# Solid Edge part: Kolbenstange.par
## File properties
Username: bmolnar
Dokumentum tartalom típus: 0
Author: bmolnar
Last saved by: bmolnar
Revision: 82
Sűrűség: 0,000 kg/m^3
Pontosság: 0,990
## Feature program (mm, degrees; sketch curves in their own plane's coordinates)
base feature "unnamed BaseFeature 1"
sketch for "unnamed Protrusion 1" plane through (42.5, 0, 0) normal (1, 0, 0) x-axis (0, 0, -1)
  circle centre (0, 0) radius 31.5
extrude "unnamed Protrusion 1" add finite 17.85 along +normal
sketch for "Kihúzás_2" #1 plane through (42.5, 0, 0) normal (1, 0, 0) x-axis (0, 0, -1)
  circle centre (0, 0) radius 8
sketch for "Kihúzás_2" #2 plane through (42.5, 0, 0) normal (1, 0, 0) x-axis (0, 0, -1)
  circle centre (0, 0) radius 31.5
extrude "Kihúzás_2" add finite 11 along -normal
sketch for "Furat_1" plane through (-17, 0, 0.0012) normal (-1, 0, 0) x-axis (0, 0, 1)
  hole centre (-0.0012, 0) bore radius 3.3235
hole "Furat_1" nominal diameter 8 finite  VBottomAngle = 118 deg; ThreadDepth = 14 mm
chamfer "Letörés_1" setback 0.7  SetBackValue2 = 45 deg
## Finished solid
Body 1: solid body, 16 faces, 22 edges, 8 vertices.
  Faces by surface: plane 8, cylinder 5, cone 2, torus 1
  Edges by curve: circle 12, line 6, curve on surface 2, ellipse 2
Bounding box of the edges (mm; curved faces can reach further): 80.350 x 63.000 x 63.000, from (-20, -31.5, -31.5) to (60.35, 31.5, 31.5).
Cylindrical faces by radius (mm): R3.3235 x2, R4.125 x1, R8 x1, R31.5 x1
Conical faces (half-angle, radius in mm at the cone's reference point): 45 deg R4.0235 x1, 59 deg R3.3235 x1
Toroidal faces (ring radius, tube radius in mm): R6.2 r1.8 x1
Planar faces by outward normal: +x 1, +y 1, -x 3, -y 1, oblique 2
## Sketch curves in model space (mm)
circle centre (42.5, 0, 0) radius 31.5
circle centre (42.5, 0, 0) radius 8
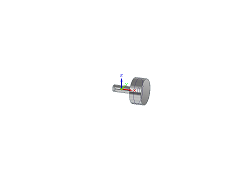
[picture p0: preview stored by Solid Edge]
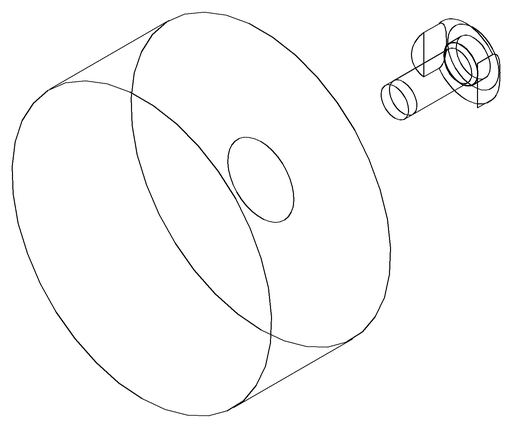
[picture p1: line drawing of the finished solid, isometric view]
